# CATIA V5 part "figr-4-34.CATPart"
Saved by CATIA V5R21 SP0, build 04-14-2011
Part number: Part1
Bounding box of the stored display mesh (mm): x 0 to 79, y -70 to 90, z -90 to 70
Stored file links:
  D:\CATIA V5R21 E-RESOURCES\CATIA-V5R21\catia-v5r21-prt\c04-catia-v5r20-prt\catia-v5r21-figr-4-33.CATPart
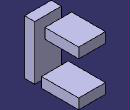
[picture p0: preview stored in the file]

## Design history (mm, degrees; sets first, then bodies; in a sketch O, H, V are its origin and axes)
Body1 (main body)
  Sketch1 on yz-plane, origin (0, 0, 0), H (0, 1, 0), V (0, 0, 1)
    line L1 (-100, 100) -> (100, 100)
    line L2 (100, 100) -> (100, -100)
    line L3 (100, -100) -> (-100, -100)
    line L4 (-100, -100) -> (-100, 100)
    line L5 (-70, 70) -> (-40, 70)
    line L6 (-40, 70) -> (-40, -90)
    line L7 (-40, -90) -> (-70, -90)
    line L8 (-70, -90) -> (-70, 70)
    line L9 (-10, 70) -> (90, 70)
    line L10 (90, 70) -> (90, 40)
    line L11 (90, 40) -> (-10, 40)
    line L12 (-10, 40) -> (-10, 70)
    point P13 (90, -90)
    line L13 (90, -90) -> (-20, -90)
    line L14 (-20, -90) -> (-20, -60)
    line L15 (-20, -60) -> (90, -60)
    line L16 (90, -60) -> (90, -90)
    horizontal: L1 H, L3 H, L5 H, L7 H, L9 H, L11 H, L13 H, L15 H
    vertical: L2 V, L4 V, L6 V, L8 V, L10 V, L12 V, L14 V, L16 V
    coincidence: P13 L10, P13 L7
  Pad1: profile edge of Sketch1, length 79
